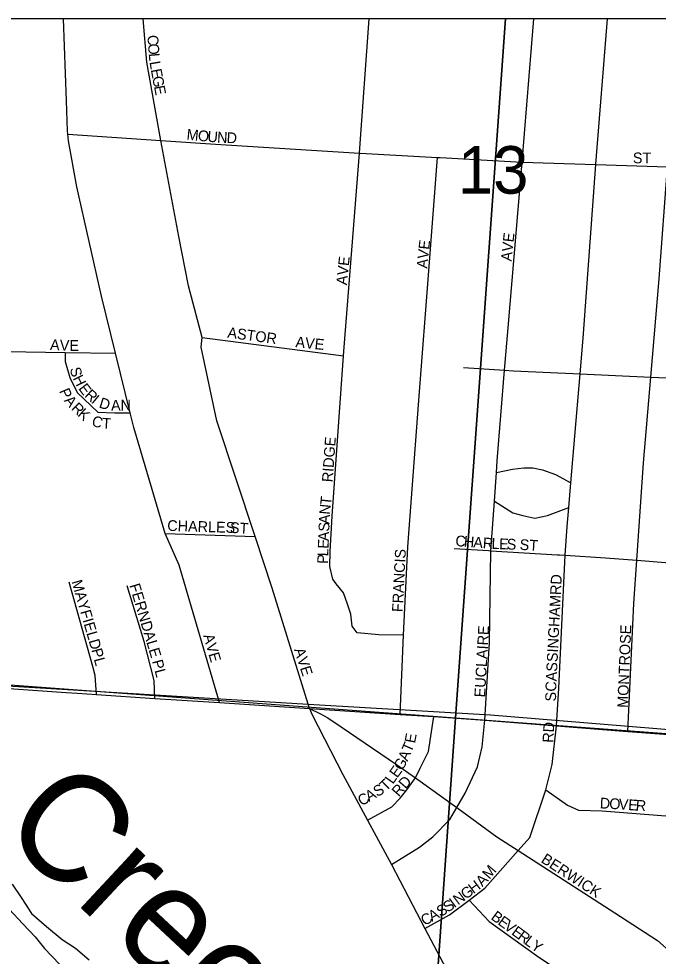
# Model space of a CAD drawing. Extents: x 0 to 34, y 0 to 22.
# Drawn here: x 3.497 to 4.06, y 20.075 to 20.9 of the extents above; entities that cross this region are included whole.
import ezdxf

# ---------------------------------------------------------------- set-up
doc = ezdxf.new("R2010")
doc.units = 0
for name, color, linetype in [('GM_X_City_Street', 7, 'Continuous'), ('GM_X_City_Street_Text', 7, 'Continuous'), ('GM_X_Corporation', 7, 'Continuous'), ('GM_X_Major_River', 7, 'Continuous'), ('GM_X_Major_River_Text', 7, 'Continuous'), ('GM_X_Section', 7, 'Continuous'), ('GM_X_Section_Text', 7, 'Continuous'), ('GM_X_US_Route', 7, 'Continuous')]:
    doc.layers.add(name, color=color, linetype=linetype)

msp = doc.modelspace()

# ---------------------------------------------------------------- linework, layer by layer
at = {"layer": 'GM_X_City_Street'}
for points in [[(3.67399, 20.29834), (3.63867, 20.41936), (3.6262, 20.44716), (3.59882, 20.54042), (3.59544, 20.55338), (3.58266, 20.60594), (3.57034, 20.65591), (3.54849, 20.75222), (3.54133, 20.79268), (3.54076, 20.79835), (3.54045, 20.80144), (3.53931, 20.82767), (3.53677, 20.9)], [(3.75339, 20.29307), (3.7522, 20.29692), (3.72046, 20.39894), (3.70546, 20.44449), (3.67191, 20.54639), (3.65812, 20.61102), (3.65898, 20.61971), (3.64688, 20.66501), (3.6382, 20.70835), (3.62259, 20.79289), (3.61008, 20.86191), (3.60688, 20.9)], [(3.79726, 20.78206), (3.80585, 20.9)], [(3.90758, 20.28288), (3.91189, 20.3512), (3.91296, 20.43196), (3.91607, 20.47547), (3.91789, 20.50085), (3.91861, 20.51103), (3.92507, 20.59085), (3.92808, 20.62807), (3.94065, 20.77389), (3.95074, 20.9)], [(3.97071, 20.27785), (3.97292, 20.31103), (3.97827, 20.42802), (3.98024, 20.45343), (3.98163, 20.47002), (3.98345, 20.49165), (3.99151, 20.58766), (3.99414, 20.61895), (4.00539, 20.77185), (4.00541, 20.77202), (4.01567, 20.9)], [(4.03344, 20.27283), (4.03892, 20.38566), (4.04153, 20.42361), (4.04743, 20.50919), (4.05387, 20.5848), (4.06123, 20.6713), (4.06849, 20.76986), (4.07808, 20.9)], [(3.54076, 20.79835), (3.62259, 20.79289), (3.67049, 20.78969), (3.79725, 20.78187), (3.79799, 20.78182), (3.86612, 20.77804), (3.86823, 20.77792)], [(3.83616, 20.35782), (3.81424, 20.35813), (3.79521, 20.35969), (3.79083, 20.36551), (3.78962, 20.37617), (3.78685, 20.38499), (3.78335, 20.39496), (3.77675, 20.40275), (3.77384, 20.40701), (3.77113, 20.4181), (3.77152, 20.43137), (3.77318, 20.46246), (3.78339, 20.60346), (3.78393, 20.61099), (3.79725, 20.78187), (3.79726, 20.78206)], [(3.83309, 20.28801), (3.83616, 20.35782), (3.83986, 20.43547), (3.84967, 20.56428), (3.85877, 20.6821), (3.86612, 20.77804)], [(3.86823, 20.77792), (3.86833, 20.77791), (3.94065, 20.77389), (4.00539, 20.77185), (4.06849, 20.76986), (4.08681, 20.76928), (4.13118, 20.76732), (4.19864, 20.76434), (4.26006, 20.76163), (4.26132, 20.76157), (4.32415, 20.75841), (4.38475, 20.75537)], [(3.65898, 20.61971), (3.78339, 20.60346)], [(3.45144, 20.60772), (3.53815, 20.60633)], [(3.53815, 20.60633), (3.58266, 20.60594)], [(3.53815, 20.60633), (3.53841, 20.59855), (3.54232, 20.58439), (3.54879, 20.57118), (3.56699, 20.55387), (3.58209, 20.55324), (3.59544, 20.55338)], [(3.88878, 20.59315), (3.92507, 20.59085), (3.93305, 20.59035), (3.99151, 20.58766), (4.05387, 20.5848), (4.11654, 20.58193), (4.13479, 20.58109), (4.18343, 20.57835), (4.23167, 20.57562), (4.24589, 20.57559), (4.24548, 20.56991), (4.31064, 20.56727), (4.31139, 20.56724), (4.34169, 20.57101), (4.37294, 20.57031), (4.4047, 20.56921)], [(3.91789, 20.50085), (3.93205, 20.50381), (3.94194, 20.50504), (3.94989, 20.50481), (3.95855, 20.50304), (3.96981, 20.49892), (3.98345, 20.49165)], [(3.91607, 20.47547), (3.93245, 20.46544), (3.9411, 20.46291), (3.95165, 20.46071), (3.96271, 20.46305), (3.96998, 20.46549), (3.98163, 20.47002)], [(3.6262, 20.44716), (3.70546, 20.44449)], [(3.88075, 20.43391), (3.91101, 20.43208), (3.91296, 20.43196)], [(3.91296, 20.43196), (3.97155, 20.42843), (3.97345, 20.42831)], [(3.97345, 20.42831), (3.97827, 20.42802), (4.01393, 20.42587), (4.04153, 20.42361), (4.10269, 20.41861), (4.15762, 20.41412), (4.17113, 20.41316), (4.2329, 20.40879), (4.27563, 20.40577), (4.29869, 20.40411), (4.35718, 20.3999), (4.36372, 20.39944), (4.36628, 20.39925)], [(3.56584, 20.30543), (3.56453, 20.32236), (3.56272, 20.33025), (3.54184, 20.4044)], [(3.6173, 20.30197), (3.61664, 20.31776), (3.60777, 20.35228), (3.59288, 20.40124)], [(3.75339, 20.29307), (3.76308, 20.28837), (3.76956, 20.28488), (3.7812, 20.27721), (3.82982, 20.24388)], [(3.75339, 20.29307), (3.83309, 20.28801), (3.86275, 20.2861), (3.90758, 20.28288), (3.97071, 20.27785), (4.03344, 20.27283), (4.09697, 20.2682), (4.1591, 20.26378), (4.22324, 20.25896), (4.29019, 20.25393), (4.35071, 20.24931), (4.38701, 20.24676), (4.44572, 20.24227), (4.56007, 20.23323), (4.62541, 20.22846), (4.69075, 20.22347), (4.75246, 20.21848), (4.81281, 20.2144), (4.84273, 20.21193)], [(3.80434, 20.19504), (3.82571, 20.20682), (3.83304, 20.21429), (3.83899, 20.22175), (3.84678, 20.23226), (3.85064, 20.24078), (3.85803, 20.2553), (3.86275, 20.2861)], [(3.82543, 20.15588), (3.85022, 20.17135), (3.862, 20.18039), (3.87692, 20.19565), (3.88289, 20.206), (3.89025, 20.21876), (3.90115, 20.24186), (3.90537, 20.25935), (3.90758, 20.28288)], [(3.85488, 20.09973), (3.87665, 20.11176), (3.89385, 20.1247), (3.9078, 20.13519), (3.93704, 20.16821), (3.94735, 20.17986), (3.96146, 20.22156), (3.96709, 20.24388), (3.97071, 20.27785)], [(3.82982, 20.24388), (3.84678, 20.23226), (3.88289, 20.206), (3.91817, 20.18033), (3.93704, 20.16821), (4.02216, 20.11356), (4.0596, 20.08914), (4.08, 20.07123)], [(3.96146, 20.22156), (3.9804, 20.20821), (3.99024, 20.20362), (4.01108, 20.20318), (4.06329, 20.19912), (4.20504, 20.18811), (4.21962, 20.191), (4.3346, 20.1782)], [(3.89385, 20.1247), (3.91149, 20.10595), (3.95307, 20.07583), (4.03928, 20.01785), (4.04759, 20.00871), (4.05475, 19.99578), (4.06941, 19.95891), (4.0743, 19.94751), (4.07996, 19.94255), (4.09432, 19.93157)]]:
    msp.add_lwpolyline(points, dxfattribs=at)
at = {"layer": 'GM_X_Corporation'}
msp.add_line((4.43361, 20.9), (3.43213, 20.9), dxfattribs=at)
msp.add_lwpolyline([(3.45333, 20.31533), (3.7522, 20.29692), (3.91257, 20.28768), (4.22345, 20.26223)], dxfattribs=at)
at = {"layer": 'GM_X_Major_River'}
for points in [[(3.49169, 20.13857), (3.50001, 20.12606), (3.50872, 20.11279), (3.52197, 20.10141), (3.5356, 20.09004), (3.54733, 20.08246), (3.55945, 20.07222)], [(3.48903, 20.11657), (3.50114, 20.10368), (3.51174, 20.0923), (3.52007, 20.08207), (3.53332, 20.06842)]]:
    msp.add_lwpolyline(points, dxfattribs=at)
at = {"layer": 'GM_X_Section'}
for p, q in [((3.92586, 20.9), (3.42043, 20.9)), ((4.42995, 20.9), (3.92586, 20.9))]:
    msp.add_line(p, q, dxfattribs=at)
for points in [[(3.42043, 20.9), (3.37876, 20.32228), (3.88174, 20.28496), (3.92586, 20.9)], [(3.92586, 20.9), (3.88174, 20.28496), (4.3834, 20.24774), (4.42995, 20.9)]]:
    msp.add_lwpolyline(points, dxfattribs=at)
for points in [[(3.88174, 20.28496), (3.81078, 19.27405), (3.30645, 19.30967), (3.37876, 20.32228)], [(4.3834, 20.24774), (4.31376, 19.23853), (3.81078, 19.27405), (3.88174, 20.28496)]]:
    msp.add_lwpolyline(points, close=True, dxfattribs=at)
at = {"layer": 'GM_X_US_Route'}
for points in [[(3.4298, 20.31472), (3.43645, 20.31414), (3.46342, 20.3125), (3.53904, 20.30724), (3.54891, 20.30657)], [(3.54891, 20.30657), (3.56584, 20.30543), (3.6173, 20.30197), (3.67399, 20.29834), (3.75339, 20.29307)], [(3.75339, 20.29307), (3.75573, 20.28761), (3.7826, 20.23519), (3.80434, 20.19504), (3.82543, 20.15588), (3.85488, 20.09973), (3.89404, 20.02537), (3.91335, 19.9888), (3.99442, 19.8346), (4.0436, 19.74101), (4.05769, 19.71328), (4.06999, 19.68923), (4.07628, 19.67708)]]:
    msp.add_lwpolyline(points, dxfattribs=at)

# ---------------------------------------------------------------- texts
at = {"layer": 'GM_X_City_Street_Text'}
for s, rotation, p in [('C', 274.15657, (3.6106, 20.88535)), ('O', 274.16765, (3.61114, 20.87787)), ('L', 275.14459, (3.61176, 20.86938)), ('L', 279.35558, (3.61245, 20.86199)), ('E', 280.64958, (3.61358, 20.85518)), ('G', 280.72758, (3.61481, 20.84861)), ('E', 280.71531, (3.61636, 20.84043)), ('M', 354.52685, (3.64483, 20.79367)), ('O', 354.50475, (3.65478, 20.79272)), ('U', 355.11648, (3.66318, 20.79191)), ('N', 357.0316, (3.67183, 20.79118)), ('D', 357.38074, (3.68022, 20.79074)), ('ST', 0.00001, (4.03799, 20.77285)), ('AVE', 84.08948, (3.93121, 20.68625)), ('E', 83.64773, (3.85865, 20.69654)), ('V', 83.73703, (3.85775, 20.68826)), ('AVE', 84.09694, (3.78622, 20.66541)), ('A', 85.03309, (3.85703, 20.68001)), ('ASTOR', 352.40504, (3.68072, 20.61949)), ('AVE', 354.09695, (3.74067, 20.61117)), ('A', 356.50136, (3.52477, 20.60867)), ('V', 358.01117, (3.53336, 20.60815)), ('E', 359.90728, (3.54203, 20.60785)), ('S', 284.77833, (3.54225, 20.59219)), ('H', 296.41875, (3.54469, 20.58378)), ('E', 307.78135, (3.54948, 20.57458)), ('P', 293.2273, (3.53278, 20.57252)), ('R', 317.91014, (3.55481, 20.56797)), ('A', 309.36047, (3.53692, 20.56391)), ('R', 316.11337, (3.54303, 20.55658)), ('I', 320.47943, (3.56073, 20.56264)), ('D', 342.66866, (3.56744, 20.5581)), ('A', 1.35624, (3.57872, 20.55515)), ('N', 0.00001, (3.58699, 20.55534)), ('K', 317.90151, (3.54867, 20.55116)), ('C', 342.4165, (3.56088, 20.54224)), ('T', 356.28001, (3.57048, 20.53951)), ('RIDGE', 85.9166, (3.77371, 20.49202)), ('T', 84.28124, (3.7721, 20.47175)), ('N', 84.74618, (3.77134, 20.46347)), ('A', 87.06992, (3.77092, 20.45525)), ('CHARLES', 358.17922, (3.62804, 20.44951)), ('ST', 356.42537, (3.6831, 20.44784)), ('S', 87.73231, (3.77066, 20.44862)), ('A', 87.72598, (3.77033, 20.44029)), ('E', 87.75629, (3.77007, 20.43363)), ('C', 355.50258, (3.88146, 20.43617)), ('H', 355.52236, (3.88894, 20.43558)), ('A', 355.49232, (3.89725, 20.43493)), ('R', 355.89164, (3.90563, 20.43427)), ('L', 357.39149, (3.91338, 20.43372)), ('E', 357.78115, (3.92011, 20.43341)), ('S', 357.80601, (3.92678, 20.43315)), ('ST', 356.42537, (3.9381, 20.43284)), ('L', 87.73231, (3.7698, 20.42696)), ('FRANCIS', 87.09084, (3.83538, 20.37782)), ('P', 87.73231, (3.76954, 20.4203)), ('MAYFIELD', 286.16188, (3.54375, 20.40486)), ('RD', 86.98901, (3.97455, 20.39282)), ('FERNDALE', 286.6981, (3.59466, 20.40158)), ('CASSINGHAM', 87.19305, (3.97038, 20.30782)), ('EUCLAIRE', 86.77387, (3.90787, 20.30281)), ('MONTROSE', 87.74074, (4.03371, 20.29363)), ('AVE', 285.94437, (3.6597, 20.35738)), ('PL', 284.92417, (3.56126, 20.34483)), ('AVE', 287.82395, (3.73968, 20.34494)), ('PL', 284.92417, (3.61468, 20.33484)), ('S', 90, (3.97037, 20.2994)), ('RD', 86.8094, (3.96788, 20.26283)), ('T', 66.33151, (3.84284, 20.25384)), ('E', 79.26502, (3.84621, 20.26218)), ('G', 61.27977, (3.83512, 20.238)), ('A', 66.79948, (3.83956, 20.2462)), ('E', 54.15742, (3.83053, 20.23151)), ('T', 44.03515, (3.82065, 20.21996)), ('L', 54.84702, (3.82671, 20.22608)), ('RD', 49.08339, (3.83193, 20.21498)), ('S', 30.24371, (3.81291, 20.21511)), ('C', 30.23895, (3.79923, 20.20714)), ('A', 30.24224, (3.80571, 20.21091)), ('D', 357.3766, (4.00871, 20.20535)), ('O', 356.34731, (4.01699, 20.20497)), ('V', 356.26007, (4.0253, 20.20444)), ('E', 356.26581, (4.03361, 20.20389)), ('R', 356.25701, (4.04027, 20.20346)), ('BERWICK', 327.05131, (3.95646, 20.15839)), ('M', 49.88476, (3.91172, 20.14242)), ('H', 36.81773, (3.89756, 20.12981)), ('A', 46.14657, (3.90549, 20.13592)), ('N', 36.51358, (3.88412, 20.11985)), ('G', 36.48528, (3.89081, 20.12481)), ('S', 34.63394, (3.875, 20.1134)), ('I', 36.33162, (3.88073, 20.11737)), ('A', 29.33879, (3.86116, 20.10546)), ('S', 30.18775, (3.86856, 20.10962)), ('C', 29.33526, (3.85462, 20.10178)), ('B', 323.60125, (3.91238, 20.10833)), ('E', 323.62768, (3.91842, 20.10387)), ('V', 323.61102, (3.92379, 20.09992)), ('E', 323.60981, (3.9305, 20.09497)), ('R', 323.62725, (3.93586, 20.09102)), ('L', 323.61102, (3.9419, 20.08657)), ('Y', 325.76398, (3.94758, 20.0824))]:
    msp.add_text(s, height=0.00947, rotation=rotation, dxfattribs=at).set_placement(p)
at = {"layer": 'GM_X_Major_River_Text'}
msp.add_text('Creek', height=0.094705, rotation=316.99149, dxfattribs=at).set_placement((3.47864, 20.18603))
at = {"layer": 'GM_X_Section_Text'}
msp.add_text('13', height=0.041856, rotation=0.00001, dxfattribs=at).set_placement((3.88382, 20.74612))

doc.saveas('drawing.dxf')
